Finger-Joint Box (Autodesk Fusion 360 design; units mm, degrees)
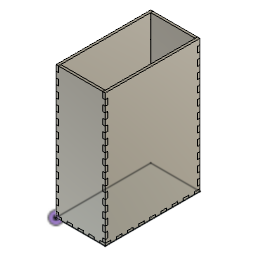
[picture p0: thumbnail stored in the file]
part number: 2025-09-15-00-10-07-891
part number: 2025-09-15-00-12-07-894
parameter "height" = 350
parameter "width" = 130
parameter "length" = 250
parameter "cboard" = 6.3
parameter "lfingerw" = 14.7059 (= "length / ( ( lfingers * 2 ) + 1 )")
parameter "wfingerw" = 14.4444 (= "width / ( ( wfingers * 2 ) + 1 )")
parameter "hfingerw" = 15.2174 (= "height / ( ( hfingers * 2 ) + 1 )")
sketch "bottom panel" plane through (0, 0, 0) normal (0, 0, 1) x axis (1, 0, 0)
  line L1 (130, 0) -> (0, 0)
  line L2 (130, 250) -> (130, 0)
  line L3 (0, 250) -> (130, 250)
  line L4 (0, 0) -> (0, 250)
  point P1 (0, 0)
  point P2 (0, 0)
  point P5 (0, 250)
  point P4 (130, 250)
  horizontal L1
  vertical L2
  horizontal L3
  vertical L4
  coincident P1 P2
  dimension "d30" distance P2 P5 = 250 (= "length")
  dimension "d31" distance P4 P5 = 130 (= "width")
extrude "Extrude4" new body sketch "bottom panel" along normal blind 6.3 (= "cboard") bodies "Bottom Panel"
sketch "bottom fingers" plane through (0, 0, 0) normal (-1, 0, 0) x axis (0, -1, 0)
  line L1 (0, 0) -> (-250, 0)
  line L2 (0, 6.3) -> (0, 0)
  line L3 (-250, 6.3) -> (0, 6.3)
  line L4 (-250, 0) -> (-250, 6.3)
  line L5 (-220.5882, 0) -> (-235.2941, 0)
  line L6 (-220.5882, 6.3) -> (-220.5882, 0)
  line L7 (-235.2941, 6.3) -> (-220.5882, 6.3)
  line L8 (-235.2941, 0) -> (-235.2941, 6.3)
  point P8 (-220.5882, 6.3)
  point P6 (-235.2941, 0)
  point P9 (-235.2941, 6.3)
  horizontal L5
  vertical L6
  horizontal L7
  vertical L8
  coincident L3 P8
  coincident L1 P6
  dimension "d34" distance P8 P9 = 14.7059 (= "lfingerw")
  dimension "d35" distance L4 L8 = 14.7059 (= "lfingerw")
extrude "Extrude5" cut sketch "bottom fingers" profile of L1 L3 L5 L6 L7 L8 no distance stored
rectangular_pattern "R-Pattern2" uSpaceDistance 205.8824 (= "length - ( lfingerw * 3 )") vSpaceDistance 0
sketch "Front Panel Sketch" plane through (0, 0, 0) normal (1, 0, 0) x axis (0, 1, 0)
  line L1 (250, 0) -> (0, 0)
  line L2 (250, 350) -> (250, 0)
  line L3 (0, 350) -> (250, 350)
  line L4 (0, 0) -> (0, 350)
  point P1 (0, 0)
  point P2 (0, 0)
  point P3 (250, 0)
  point P4 (250, 350)
  perpendicular L1 L2
  parallel L1 L3
  parallel L2 L4
  horizontal L1
  coincident P1 P2
  dimension "d42" distance P3 P4 = 350 (= "height")
extrude "Extrude6" new body sketch "Front Panel Sketch" along normal blind 6.3 (= "cboard") bodies "Front Panel"
combine "Combine1"
sketch "front panel right fingers" plane through (0, 0, 0) normal (0, -1, 0) x axis (1, 0, 0)
  line L1 (6.3, 6.3) -> (0, 6.3)
  line L2 (6.3, 350) -> (6.3, 6.3)
  line L3 (0, 350) -> (6.3, 350)
  line L4 (0, 6.3) -> (0, 350)
  line L5 (6.3, 15.2174) -> (0, 15.2174)
  line L6 (6.3, 30.4348) -> (6.3, 15.2174)
  line L7 (0, 30.4348) -> (6.3, 30.4348)
  line L8 (0, 15.2174) -> (0, 30.4348)
  line L9 (130, 0) -> (0, 0)
  point P8 (6.3, 30.4348)
  point P6 (0, 15.2174)
  point P9 (0, 30.4348)
  horizontal L5
  vertical L6
  horizontal L7
  vertical L8
  coincident L2 P8
  coincident L4 P6
  dimension "d45" distance P6 P9 = 15.2174 (= "hfingerw")
  dimension "d46" distance L5 L9 = 15.2174 (= "hfingerw")
extrude "Extrude7" cut sketch "front panel right fingers" profile of L2 L4 L5 L6 L7 L8 no distance stored
rectangular_pattern "R-Pattern3" uSpaceDistance 304.3478 (= "height - ( hfingerw * 3 )") vSpaceDistance 0
combine "Combine3"
extrude "Extrude9" of existing geometry no distance stored bodies "Back Panel"
combine "Combine4"
sketch "left panel sketch" plane through (0, 0, 0) normal (0, 1, 0) x axis (1, 0, 0)
  line L1 (130, 0) -> (0, 0)
  line L2 (130, -350) -> (130, 0)
  line L3 (0, -350) -> (130, -350)
  line L4 (0, 0) -> (0, -350)
  point P1 (0, 0)
  point P2 (0, 0)
  perpendicular L1 L2
  parallel L1 L3
  parallel L2 L4
  horizontal L1
  coincident P1 P2
extrude "Extrude10" new body sketch "left panel sketch" along normal blind 6.3 (= "cboard") bodies "Left Panel"
sketch "bottom panel left fingers" plane through (0, 0, 0) normal (0, -1, 0) x axis (1, 0, 0)
  line L1 (130, 0) -> (0, 0)
  line L2 (130, 6.3) -> (130, 0)
  line L3 (0, 6.3) -> (130, 6.3)
  line L4 (0, 0) -> (0, 6.3)
  line L5 (28.8889, 0) -> (14.4444, 0)
  line L6 (28.8889, 6.3) -> (28.8889, 0)
  line L7 (14.4444, 6.3) -> (28.8889, 6.3)
  line L8 (14.4444, 0) -> (14.4444, 6.3)
  point P8 (28.8889, 6.3)
  point P6 (14.4444, 0)
  point P9 (14.4444, 6.3)
  horizontal L5
  vertical L6
  horizontal L7
  vertical L8
  coincident L3 P8
  coincident L1 P6
  dimension "d61" distance P8 P9 = 14.4444 (= "wfingerw")
  dimension "d62" distance L4 L8 = 14.4444 (= "wfingerw")
extrude "Extrude11" cut sketch "bottom panel left fingers" profile of L1 L3 L5 L6 L7 L8 no distance stored
rectangular_pattern "R-Pattern4" uSpaceDistance -86.6667 (= "-( ( width - wfingerw * 3 ) )") vSpaceDistance 0
combine "Combine5"
extrude "Extrude12" of existing geometry no distance stored bodies "Right Panel"
combine "Combine6"
combine "Combine7"
combine "Combine8"
extrude "Extrude1" new body blind 6.3 (= "cboard") bodies "Bottom Panel"
sketch "Bottom Panel Front Fingers Sketch" plane through (65, 0, 0) normal (1, 0, 0) x axis (0, 1, 0)
  line L1 (125, 0) -> (-125, 0)
  line L2 (125, 6.3) -> (125, 0)
  line L3 (-125, 6.3) -> (125, 6.3)
  line L4 (-125, 0) -> (-125, 6.3)
  line L5 (-95.5882, 0) -> (-110.2941, 0)
  line L6 (-95.5882, 6.3) -> (-95.5882, 0)
  line L7 (-110.2941, 6.3) -> (-95.5882, 6.3)
  line L8 (-110.2941, 0) -> (-110.2941, 6.3)
  point P8 (-95.5882, 6.3)
  point P6 (-110.2941, 0)
  point P9 (-110.2941, 6.3)
  horizontal L5
  vertical L6
  horizontal L7
  vertical L8
  coincident L3 P8
  coincident L1 P6
  dimension "d17" distance P8 P9 = 14.7059 (= "lfingerw")
  dimension "d18" distance L4 L8 = 14.7059 (= "lfingerw")
extrude "Extrude2" cut sketch "Bottom Panel Front Fingers Sketch" profile of L1 L3 L5 L6 L7 L8 no distance stored
rectangular_pattern "R-Pattern1" uSpaceDistance 205.882 vSpaceDistance 0
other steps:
create_component "CreateComponent1"
named bodies: "Bottom Panel", "Front Panel", "Back Panel", "Left Panel", "Right Panel"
